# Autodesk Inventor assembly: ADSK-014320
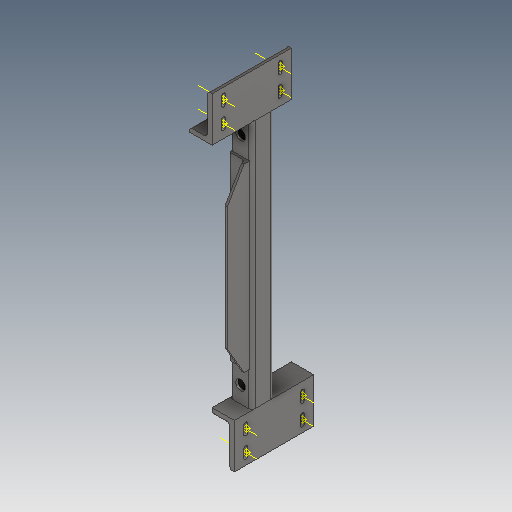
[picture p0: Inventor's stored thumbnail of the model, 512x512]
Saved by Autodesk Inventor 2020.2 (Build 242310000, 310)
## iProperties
Part Number: ADSK-014320
Description: Phantom-Baugruppe
Document SubType Name: Baugruppe
Designer: lutzd
Mass: 8826.2 g
Surface Area: 3683.3 cm^2
Volume: 1124.36 cm^3
Density: 7.85 g/cm^3
DocNumber: ADSK-014320
Folder: .
Dimensions: 760x228x50 mm
Mass: 8,826 kg
_FrameDoc: Frame Assembly
_Version: 15.0.0
Title: Gestellbaugruppen
Author: lutzd
Revision Number: -
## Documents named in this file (5)
- D:\07 - DEMODATEN\OTX 2019 - Dataset - UPDATE - Dez2019\Designs\07-Packing machine\500571\Frame\ADSK-014320.iam
- D:\07 - DEMODATEN\OTX 2019 - Dataset - UPDATE - Dez2019\Designs\07-Packing machine\500571\Frame\ADSK-014323.ipt
- D:\07 - DEMODATEN\OTX 2019 - Dataset - UPDATE - Dez2019\Designs\07-Packing machine\500571\Frame\ADSK-014322.ipt
- D:\07 - DEMODATEN\OTX 2019 - Dataset - UPDATE - Dez2019\Designs\07-Packing machine\500571\Frame\ADSK-014321.ipt
- D:\07 - DEMODATEN\OTX 2019 - Dataset - UPDATE - Dez2019\Designs\07-Packing machine\500571\Frame\ADSK-014324.ipt
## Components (5 placed, 4 different names)
1. Gestellreferenzmodell
2. DIN 50 x 50 x 5:1
3. ISO 50x40x5:1
4. ISO 100x50x10:1
5. ISO 100x50x10:2
